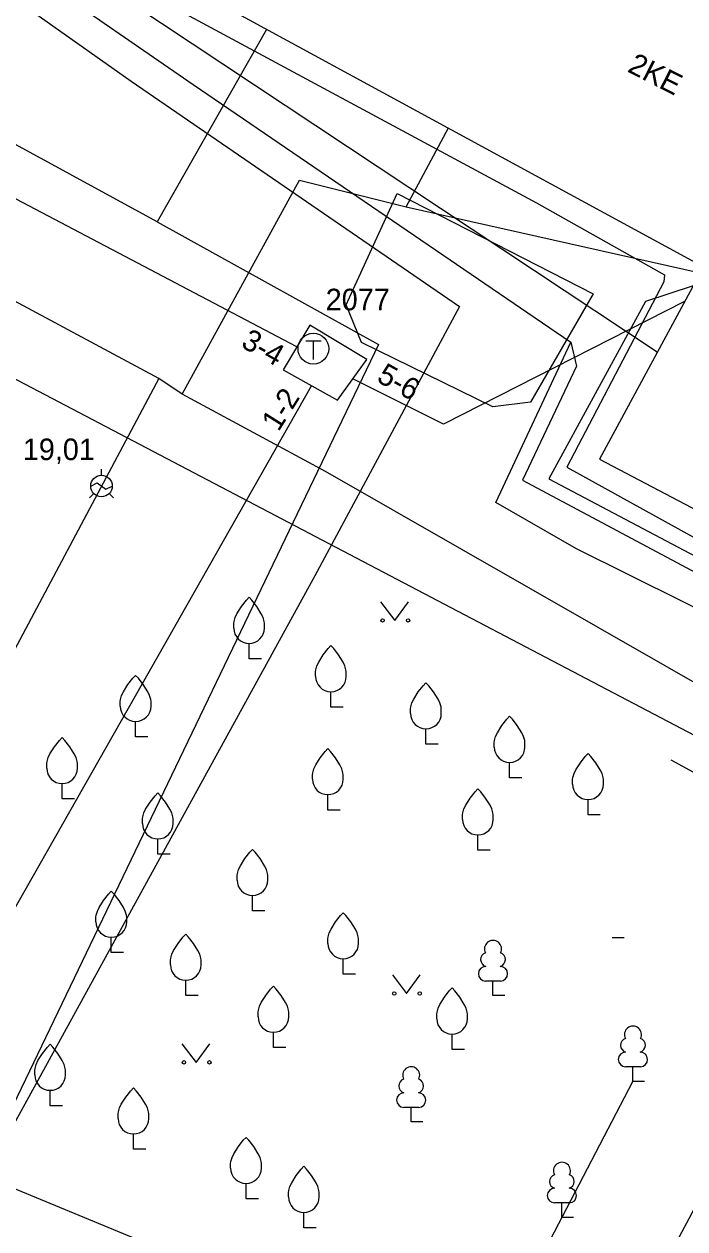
# Model space of a CAD drawing. Extents: x 713497 to 713863, y 6590062 to 6590327.
# Drawn here: x 713784.91 to 713806.4, y 6590085.09 to 6590124.29 of the extents above; entities that cross this region are included whole.
import ezdxf

# ---------------------------------------------------------------- set-up
doc = ezdxf.new("R2010")
doc.units = 0
for name, color, linetype in [('HALJASTUS', 7, 'Continuous'), ('HOONE', 7, 'Continuous'), ('HOONEDET', 7, 'Continuous'), ('KORGUS', 7, 'Continuous'), ('KPKAABEL', 7, 'Continuous'), ('MPKAABEL', 7, 'Continuous'), ('PUU', 7, 'Continuous'), ('SIKAEV', 7, 'Continuous'), ('SITRASS', 7, 'Continuous'), ('TEE', 7, 'Continuous'), ('TKAEV', 7, 'Continuous'), ('TORU NR', 7, 'Continuous'), ('TTRASS', 7, 'Continuous'), ('По умолчанию', 7, 'Continuous'), ('Слой 1', 7, 'Continuous')]:
    doc.layers.add(name, color=color, linetype=linetype)

msp = doc.modelspace()

# ---------------------------------------------------------------- linework, layer by layer
at = {"layer": 'HALJASTUS'}
for p, q in [((713796.507, 6590105.497), (713796.97, 6590104.89)), ((713796.97, 6590104.89), (713797.416, 6590105.497)), ((713796.887, 6590093.357), (713797.35, 6590092.75)), ((713797.35, 6590092.75), (713797.796, 6590093.357)), ((713790.047, 6590091.117), (713790.51, 6590090.51)), ((713790.51, 6590090.51), (713790.956, 6590091.117))]:
    msp.add_line(p, q, dxfattribs=at)
for points in [[(713808.833, 6590098.769), (713805.953, 6590100.341)], [(713791.148, 6590077.413), (713796.678, 6590074.465), (713804.711, 6590089.892)]]:
    msp.add_lwpolyline(points, dxfattribs=at)
for centre in [(713796.569, 6590104.89), (713797.398, 6590104.89), (713796.949, 6590092.75), (713797.778, 6590092.75), (713790.109, 6590090.51), (713790.938, 6590090.51)]:
    msp.add_circle(centre, 0.055, dxfattribs=at)
at = {"layer": 'HOONE'}
for p, q in [((713787.43, 6590109.61), (713787.43, 6590109.807)), ((713787.08, 6590109.258), (713787.291, 6590109.364)), ((713787.291, 6590109.364), (713787.569, 6590109.156)), ((713787.569, 6590109.156), (713787.78, 6590109.262)), ((713787.183, 6590109.013), (713787.043, 6590108.873)), ((713787.677, 6590109.013), (713787.817, 6590108.873))]:
    msp.add_line(p, q, dxfattribs=at)
for points in [[(713812.78, 6590105.321), (713821.155, 6590121.073), (713794.711, 6590135.132), (713790, 6590125.65), (713807, 6590116.39), (713803.62, 6590110.13), (713812.78, 6590105.321)], [(713789.29, 6590112.76), (713764.71, 6590125.97), (713755.23, 6590131.21)], [(713797.34, 6590118.35), (713798.71, 6590120.91)], [(713790.05, 6590112.25), (713793.87, 6590119.21), (713797.34, 6590118.35)], [(713797.34, 6590118.35), (713806.9, 6590116.2)], [(713789.29, 6590112.76), (713771.86, 6590079.97)], [(713790.05, 6590112.25), (713789.29, 6590112.76)], [(713808.017, 6590102.118), (713794.71, 6590109.73), (713790.05, 6590112.25)]]:
    msp.add_lwpolyline(points, dxfattribs=at)
msp.add_circle((713787.43, 6590109.26), 0.35, dxfattribs=at)
at = {"layer": 'HOONEDET'}
msp.add_lwpolyline([(713814.782, 6590106.918), (713822.414, 6590121.274), (713794.494, 6590136.038), (713792.632, 6590132.516), (713792.607, 6590132.517), (713788.73, 6590125.41), (713801.57, 6590118.48), (713805.74, 6590116.13), (713805.72, 6590115.91), (713802.56, 6590109.88), (713810.794, 6590105.321), (713813.751, 6590103.7)], dxfattribs=at)
at = {"layer": 'KPKAABEL'}
msp.add_lwpolyline([(713773.44, 6590139.89), (713762.88, 6590120.59), (713775.24, 6590090.28), (713794.548, 6590082.284), (713800.542, 6590079.311), (713832.311, 6590062.302)], dxfattribs=at)
at = {"layer": 'MPKAABEL'}
for points in [[(713781.077, 6590168.981), (713778.842, 6590164.352), (713775.042, 6590156.623), (713771.019, 6590147.665), (713770.454, 6590144.893), (713769.354, 6590143.636), (713766.17, 6590138.15), (713788.39, 6590122.43), (713799.07, 6590115.1), (713794.37, 6590106.34), (713776.17, 6590073.19)], [(713772.142, 6590144.788), (713771.22, 6590145.17), (713770.034, 6590143.288), (713767, 6590138.47), (713790.41, 6590122.33), (713802.69, 6590113.94)], [(713805.5, 6590113.62), (713775.25, 6590133.69), (713767.93, 6590138.65), (713770.628, 6590142.984), (713771.69, 6590144.69), (713771.988, 6590144.513)], [(713817.767, 6590100.143), (713814.15, 6590101.61), (713809.839, 6590103.754), (713802.87, 6590107.22), (713800.25, 6590108.73), (713802.69, 6590113.94)], [(713802.69, 6590113.94), (713802.87, 6590113.16), (713801.12, 6590109.45), (713810.319, 6590104.541), (713819.99, 6590099.38), (713832.692, 6590092.656)]]:
    msp.add_lwpolyline(points, dxfattribs=at)
at = {"layer": 'PUU'}
for p, q in [((713792.23, 6590103.64), (713792.23, 6590104.14)), ((713792.63, 6590103.64), (713792.23, 6590103.64)), ((713794.89, 6590102.07), (713794.89, 6590102.57)), ((713795.29, 6590102.07), (713794.89, 6590102.07)), ((713788.54, 6590101.1), (713788.54, 6590101.6)), ((713797.98, 6590100.86), (713797.98, 6590101.36)), ((713788.94, 6590101.1), (713788.54, 6590101.1)), ((713798.38, 6590100.86), (713797.98, 6590100.86)), ((713800.7, 6590099.77), (713800.7, 6590100.27)), ((713801.1, 6590099.77), (713800.7, 6590099.77)), ((713786.15, 6590099.08), (713786.15, 6590099.58)), ((713786.55, 6590099.08), (713786.15, 6590099.08)), ((713794.79, 6590098.72), (713794.79, 6590099.22)), ((713803.25, 6590098.56), (713803.25, 6590099.06)), ((713795.19, 6590098.72), (713794.79, 6590098.72)), ((713803.65, 6590098.56), (713803.25, 6590098.56)), ((713799.67, 6590097.41), (713799.67, 6590097.91)), ((713789.26, 6590097.28), (713789.26, 6590097.78)), ((713800.07, 6590097.41), (713799.67, 6590097.41)), ((713789.66, 6590097.28), (713789.26, 6590097.28)), ((713792.34, 6590095.44), (713792.34, 6590095.94)), ((713792.74, 6590095.44), (713792.34, 6590095.44)), ((713787.75, 6590094.08), (713787.75, 6590094.58)), ((713804.43, 6590094.56), (713804.396, 6590094.56)), ((713788.15, 6590094.08), (713787.75, 6590094.08)), ((713795.29, 6590093.38), (713795.29, 6590093.88)), ((713790.17, 6590092.68), (713790.17, 6590093.18)), ((713795.69, 6590093.38), (713795.29, 6590093.38)), ((713800.4, 6590093.155), (713799.92, 6590093.155)), ((713800.16, 6590092.68), (713800.16, 6590093.155)), ((713790.57, 6590092.68), (713790.17, 6590092.68)), ((713800.54, 6590092.68), (713800.16, 6590092.68)), ((713793.02, 6590090.99), (713793.02, 6590091.49)), ((713798.83, 6590090.93), (713798.83, 6590091.43)), ((713793.42, 6590090.99), (713793.02, 6590090.99)), ((713799.23, 6590090.93), (713798.83, 6590090.93)), ((713804.951, 6590090.367), (713804.471, 6590090.367)), ((713804.711, 6590089.892), (713804.711, 6590090.367)), ((713785.76, 6590089.1), (713785.76, 6590089.6)), ((713805.091, 6590089.892), (713804.711, 6590089.892)), ((713786.16, 6590089.1), (713785.76, 6590089.1)), ((713797.74, 6590089.045), (713797.26, 6590089.045)), ((713797.5, 6590088.57), (713797.5, 6590089.045)), ((713797.88, 6590088.57), (713797.5, 6590088.57)), ((713788.47, 6590087.68), (713788.47, 6590088.18)), ((713788.87, 6590087.68), (713788.47, 6590087.68)), ((713792.13, 6590086.07), (713792.13, 6590086.57)), ((713792.53, 6590086.07), (713792.13, 6590086.07)), ((713802.641, 6590085.937), (713802.161, 6590085.937)), ((713802.401, 6590085.462), (713802.401, 6590085.937)), ((713794.01, 6590085.13), (713794.01, 6590085.63)), ((713802.781, 6590085.462), (713802.401, 6590085.462)), ((713794.41, 6590085.13), (713794.01, 6590085.13))]:
    msp.add_line(p, q, dxfattribs=at)
for points in [[(713791.73, 6590104.64), (713791.73, 6590104.79), (713791.74, 6590104.855), (713791.775, 6590104.985), (713791.835, 6590105.105), (713791.98, 6590105.34), (713792.14, 6590105.545), (713792.23, 6590105.64)], [(713792.73, 6590104.64), (713792.73, 6590104.79), (713792.72, 6590104.855), (713792.685, 6590104.985), (713792.625, 6590105.105), (713792.48, 6590105.34), (713792.32, 6590105.545), (713792.23, 6590105.64)], [(713794.39, 6590103.07), (713794.39, 6590103.22), (713794.4, 6590103.285), (713794.435, 6590103.415), (713794.495, 6590103.535), (713794.64, 6590103.77), (713794.8, 6590103.975), (713794.89, 6590104.07)], [(713795.39, 6590103.07), (713795.39, 6590103.22), (713795.38, 6590103.285), (713795.345, 6590103.415), (713795.285, 6590103.535), (713795.14, 6590103.77), (713794.98, 6590103.975), (713794.89, 6590104.07)], [(713788.04, 6590102.1), (713788.04, 6590102.25), (713788.05, 6590102.315), (713788.085, 6590102.445), (713788.145, 6590102.565), (713788.29, 6590102.8), (713788.45, 6590103.005), (713788.54, 6590103.1)], [(713789.04, 6590102.1), (713789.04, 6590102.25), (713789.03, 6590102.315), (713788.995, 6590102.445), (713788.935, 6590102.565), (713788.79, 6590102.8), (713788.63, 6590103.005), (713788.54, 6590103.1)], [(713797.48, 6590101.86), (713797.48, 6590102.01), (713797.49, 6590102.075), (713797.525, 6590102.205), (713797.585, 6590102.325), (713797.73, 6590102.56), (713797.89, 6590102.765), (713797.98, 6590102.86)], [(713798.48, 6590101.86), (713798.48, 6590102.01), (713798.47, 6590102.075), (713798.435, 6590102.205), (713798.375, 6590102.325), (713798.23, 6590102.56), (713798.07, 6590102.765), (713797.98, 6590102.86)], [(713800.2, 6590100.77), (713800.2, 6590100.92), (713800.21, 6590100.985), (713800.245, 6590101.115), (713800.305, 6590101.235), (713800.45, 6590101.47), (713800.61, 6590101.675), (713800.7, 6590101.77)], [(713801.2, 6590100.77), (713801.2, 6590100.92), (713801.19, 6590100.985), (713801.155, 6590101.115), (713801.095, 6590101.235), (713800.95, 6590101.47), (713800.79, 6590101.675), (713800.7, 6590101.77)], [(713785.65, 6590100.08), (713785.65, 6590100.23), (713785.66, 6590100.295), (713785.695, 6590100.425), (713785.755, 6590100.545), (713785.9, 6590100.78), (713786.06, 6590100.985), (713786.15, 6590101.08)], [(713786.65, 6590100.08), (713786.65, 6590100.23), (713786.64, 6590100.295), (713786.605, 6590100.425), (713786.545, 6590100.545), (713786.4, 6590100.78), (713786.24, 6590100.985), (713786.15, 6590101.08)], [(713794.29, 6590099.72), (713794.29, 6590099.87), (713794.3, 6590099.935), (713794.335, 6590100.065), (713794.395, 6590100.185), (713794.54, 6590100.42), (713794.7, 6590100.625), (713794.79, 6590100.72)], [(713795.29, 6590099.72), (713795.29, 6590099.87), (713795.28, 6590099.935), (713795.245, 6590100.065), (713795.185, 6590100.185), (713795.04, 6590100.42), (713794.88, 6590100.625), (713794.79, 6590100.72)], [(713802.75, 6590099.56), (713802.75, 6590099.71), (713802.76, 6590099.775), (713802.795, 6590099.905), (713802.855, 6590100.025), (713803, 6590100.26), (713803.16, 6590100.465), (713803.25, 6590100.56)], [(713803.75, 6590099.56), (713803.75, 6590099.71), (713803.74, 6590099.775), (713803.705, 6590099.905), (713803.645, 6590100.025), (713803.5, 6590100.26), (713803.34, 6590100.465), (713803.25, 6590100.56)], [(713799.17, 6590098.41), (713799.17, 6590098.56), (713799.18, 6590098.625), (713799.215, 6590098.755), (713799.275, 6590098.875), (713799.42, 6590099.11), (713799.58, 6590099.315), (713799.67, 6590099.41)], [(713800.17, 6590098.41), (713800.17, 6590098.56), (713800.16, 6590098.625), (713800.125, 6590098.755), (713800.065, 6590098.875), (713799.92, 6590099.11), (713799.76, 6590099.315), (713799.67, 6590099.41)], [(713788.76, 6590098.28), (713788.76, 6590098.43), (713788.77, 6590098.495), (713788.805, 6590098.625), (713788.865, 6590098.745), (713789.01, 6590098.98), (713789.17, 6590099.185), (713789.26, 6590099.28)], [(713789.76, 6590098.28), (713789.76, 6590098.43), (713789.75, 6590098.495), (713789.715, 6590098.625), (713789.655, 6590098.745), (713789.51, 6590098.98), (713789.35, 6590099.185), (713789.26, 6590099.28)], [(713791.84, 6590096.44), (713791.84, 6590096.59), (713791.85, 6590096.655), (713791.885, 6590096.785), (713791.945, 6590096.905), (713792.09, 6590097.14), (713792.25, 6590097.345), (713792.34, 6590097.44)], [(713792.84, 6590096.44), (713792.84, 6590096.59), (713792.83, 6590096.655), (713792.795, 6590096.785), (713792.735, 6590096.905), (713792.59, 6590097.14), (713792.43, 6590097.345), (713792.34, 6590097.44)], [(713787.25, 6590095.08), (713787.25, 6590095.23), (713787.26, 6590095.295), (713787.295, 6590095.425), (713787.355, 6590095.545), (713787.5, 6590095.78), (713787.66, 6590095.985), (713787.75, 6590096.08)], [(713788.25, 6590095.08), (713788.25, 6590095.23), (713788.24, 6590095.295), (713788.205, 6590095.425), (713788.145, 6590095.545), (713788, 6590095.78), (713787.84, 6590095.985), (713787.75, 6590096.08)], [(713794.79, 6590094.38), (713794.79, 6590094.53), (713794.8, 6590094.595), (713794.835, 6590094.725), (713794.895, 6590094.845), (713795.04, 6590095.08), (713795.2, 6590095.285), (713795.29, 6590095.38)], [(713795.79, 6590094.38), (713795.79, 6590094.53), (713795.78, 6590094.595), (713795.745, 6590094.725), (713795.685, 6590094.845), (713795.54, 6590095.08), (713795.38, 6590095.285), (713795.29, 6590095.38)], [(713789.67, 6590093.68), (713789.67, 6590093.83), (713789.68, 6590093.895), (713789.715, 6590094.025), (713789.775, 6590094.145), (713789.92, 6590094.38), (713790.08, 6590094.585), (713790.17, 6590094.68)], [(713790.67, 6590093.68), (713790.67, 6590093.83), (713790.66, 6590093.895), (713790.625, 6590094.025), (713790.565, 6590094.145), (713790.42, 6590094.38), (713790.26, 6590094.585), (713790.17, 6590094.68)], [(713792.52, 6590091.99), (713792.52, 6590092.14), (713792.53, 6590092.205), (713792.565, 6590092.335), (713792.625, 6590092.455), (713792.77, 6590092.69), (713792.93, 6590092.895), (713793.02, 6590092.99)], [(713793.52, 6590091.99), (713793.52, 6590092.14), (713793.51, 6590092.205), (713793.475, 6590092.335), (713793.415, 6590092.455), (713793.27, 6590092.69), (713793.11, 6590092.895), (713793.02, 6590092.99)], [(713798.33, 6590091.93), (713798.33, 6590092.08), (713798.34, 6590092.145), (713798.375, 6590092.275), (713798.435, 6590092.395), (713798.58, 6590092.63), (713798.74, 6590092.835), (713798.83, 6590092.93)], [(713799.33, 6590091.93), (713799.33, 6590092.08), (713799.32, 6590092.145), (713799.285, 6590092.275), (713799.225, 6590092.395), (713799.08, 6590092.63), (713798.92, 6590092.835), (713798.83, 6590092.93)], [(713785.26, 6590090.1), (713785.26, 6590090.25), (713785.27, 6590090.315), (713785.305, 6590090.445), (713785.365, 6590090.565), (713785.51, 6590090.8), (713785.67, 6590091.005), (713785.76, 6590091.1)], [(713786.26, 6590090.1), (713786.26, 6590090.25), (713786.25, 6590090.315), (713786.215, 6590090.445), (713786.155, 6590090.565), (713786.01, 6590090.8), (713785.85, 6590091.005), (713785.76, 6590091.1)], [(713787.97, 6590088.68), (713787.97, 6590088.83), (713787.98, 6590088.895), (713788.015, 6590089.025), (713788.075, 6590089.145), (713788.22, 6590089.38), (713788.38, 6590089.585), (713788.47, 6590089.68)], [(713788.97, 6590088.68), (713788.97, 6590088.83), (713788.96, 6590088.895), (713788.925, 6590089.025), (713788.865, 6590089.145), (713788.72, 6590089.38), (713788.56, 6590089.585), (713788.47, 6590089.68)], [(713791.63, 6590087.07), (713791.63, 6590087.22), (713791.64, 6590087.285), (713791.675, 6590087.415), (713791.735, 6590087.535), (713791.88, 6590087.77), (713792.04, 6590087.975), (713792.13, 6590088.07)], [(713792.63, 6590087.07), (713792.63, 6590087.22), (713792.62, 6590087.285), (713792.585, 6590087.415), (713792.525, 6590087.535), (713792.38, 6590087.77), (713792.22, 6590087.975), (713792.13, 6590088.07)], [(713793.51, 6590086.13), (713793.51, 6590086.28), (713793.52, 6590086.345), (713793.555, 6590086.475), (713793.615, 6590086.595), (713793.76, 6590086.83), (713793.92, 6590087.035), (713794.01, 6590087.13)], [(713794.51, 6590086.13), (713794.51, 6590086.28), (713794.5, 6590086.345), (713794.465, 6590086.475), (713794.405, 6590086.595), (713794.26, 6590086.83), (713794.1, 6590087.035), (713794.01, 6590087.13)]]:
    msp.add_lwpolyline(points, dxfattribs=at)
for centre, radius, start, end in [((713792.23, 6590104.64), 0.5, 180, 0), ((713794.89, 6590103.07), 0.5, 180, 0), ((713788.54, 6590102.1), 0.5, 180, 0), ((713797.98, 6590101.86), 0.5, 180, 0), ((713800.7, 6590100.77), 0.5, 180, 0), ((713786.15, 6590100.08), 0.5, 180, 0), ((713794.79, 6590099.72), 0.5, 180, 0), ((713803.25, 6590099.56), 0.5, 180, 0), ((713789.26, 6590098.28), 0.5, 180, 0), ((713799.67, 6590098.41), 0.5, 180, 0), ((713792.34, 6590096.44), 0.5, 180, 0), ((713787.75, 6590095.08), 0.5, 180, 0), ((713795.29, 6590094.38), 0.5, 180, 0), ((713800.16, 6590094.2), 0.277, 332.5799, 207.4201), ((713799.99, 6590093.853), 0.233, 109.0217, 253.1415), ((713800.33, 6590093.853), 0.233, 286.8508, 70.9859), ((713790.17, 6590093.68), 0.5, 180, 0), ((713799.923, 6590093.392), 0.238, 90.0016, 269.3953), ((713800.397, 6590093.392), 0.238, 270.6047, 89.9984), ((713793.02, 6590091.99), 0.5, 180, 0), ((713798.83, 6590091.93), 0.5, 180, 0), ((713804.711, 6590091.412), 0.277, 332.5799, 207.4201), ((713804.541, 6590091.064), 0.233, 109.0217, 253.1415), ((713804.881, 6590091.064), 0.233, 286.8508, 70.9859), ((713804.473, 6590090.604), 0.238, 90.0016, 269.3953), ((713804.948, 6590090.604), 0.238, 270.6047, 89.9984), ((713797.5, 6590090.09), 0.277, 332.5799, 207.4201), ((713785.76, 6590090.1), 0.5, 180, 0), ((713797.33, 6590089.743), 0.233, 109.0217, 253.1415), ((713797.67, 6590089.743), 0.233, 286.8508, 70.9859), ((713797.263, 6590089.282), 0.238, 90.0016, 269.3953), ((713797.737, 6590089.282), 0.238, 270.6047, 89.9984), ((713788.47, 6590088.68), 0.5, 180, 0), ((713802.401, 6590086.982), 0.277, 332.5799, 207.4201), ((713792.13, 6590087.07), 0.5, 180, 0), ((713802.231, 6590086.635), 0.233, 109.0217, 253.1415), ((713802.571, 6590086.635), 0.233, 286.8508, 70.9859), ((713794.01, 6590086.13), 0.5, 180, 0), ((713802.164, 6590086.175), 0.238, 90.0016, 269.3953), ((713802.639, 6590086.175), 0.238, 270.6047, 89.9984)]:
    msp.add_arc(centre, radius, start, end, dxfattribs=at)
at = {"layer": 'SITRASS'}
for points in [[(713789.24, 6590117.86), (713783.55, 6590120.96), (713761.9, 6590133.51)], [(713792.8, 6590124.12), (713789.24, 6590117.86)], [(713789.24, 6590117.86), (713796.44, 6590113.87), (713777.82, 6590075.09), (713780.8, 6590073.4), (713780.86, 6590073.4), (713783.727, 6590071.899), (713786.611, 6590070.388), (713789.07, 6590069.1), (713785.468, 6590062.302)], [(713806.67, 6590115.77), (713805.12, 6590115.27), (713801.98, 6590109.5), (713810.568, 6590104.949), (713810.568, 6590104.949), (713832.983, 6590093.161), (713833.016, 6590093.133), (713841.98, 6590088.44)]]:
    msp.add_lwpolyline(points, dxfattribs=at)
at = {"layer": 'TEE'}
for points in [[(713803.412, 6590115.509), (713801.38, 6590111.994), (713800.155, 6590111.839), (713795.889, 6590113.928), (713795.39, 6590115.159), (713797.045, 6590118.78), (713803.412, 6590115.509)], [(713813.27, 6590097.299), (713812.51, 6590096.599), (713799.828, 6590072.901), (713794.153, 6590062.302)]]:
    msp.add_lwpolyline(points, dxfattribs=at)
at = {"layer": 'TKAEV'}
for p, q in [((713794.07, 6590113.98), (713794.57, 6590113.98)), ((713794.32, 6590113.38), (713794.32, 6590113.98))]:
    msp.add_line(p, q, dxfattribs=at)
msp.add_circle((713794.32, 6590113.73), 0.5, dxfattribs=at)
at = {"layer": 'TTRASS'}
for points in [[(713793.78, 6590113.79), (713759.97, 6590131.6)], [(713806.39, 6590115.26), (713798.55, 6590111.27), (713795.6, 6590112.75)], [(713794.2, 6590114.5), (713793.34, 6590113.04), (713795.1, 6590112.05), (713796.06, 6590113.38), (713794.2, 6590114.5)], [(713770.92, 6590070.88), (713771.86, 6590073.05), (713794.26, 6590112.52)]]:
    msp.add_lwpolyline(points, dxfattribs=at)
at = {"layer": 'По умолчанию'}
msp.add_line((713804.396, 6590094.56), (713804.03, 6590094.56), dxfattribs=at)
at = {"layer": 'Слой 1'}
msp.add_lwpolyline([(713824.52, 6590122.4), (713811.57, 6590098.6), (713775.69, 6590117.42), (713779.01, 6590124.36), (713787.58, 6590142.43)], close=True, dxfattribs=at)

# ---------------------------------------------------------------- texts
at = {"layer": 'HOONE'}
msp.add_text('2KE', height=0.7, rotation=332.9569, dxfattribs=at).set_placement((713804.499, 6590122.759))
at = {"layer": 'KORGUS'}
msp.add_text('19,01', height=0.7, dxfattribs=at).set_placement((713784.872, 6590110.105))
at = {"layer": 'SIKAEV'}
msp.add_text('2077', height=0.7, dxfattribs=at).set_placement((713794.72, 6590114.98))
at = {"layer": 'TORU NR'}
for s, rotation, p in [('3-4', 330.7145, (713791.931, 6590113.803)), ('5-6', 330.7145, (713796.341, 6590112.683)), ('1-2', 57.8344, (713793.184, 6590111.007))]:
    msp.add_text(s, height=0.7, rotation=rotation, dxfattribs=at).set_placement(p)

doc.saveas('drawing.dxf')
